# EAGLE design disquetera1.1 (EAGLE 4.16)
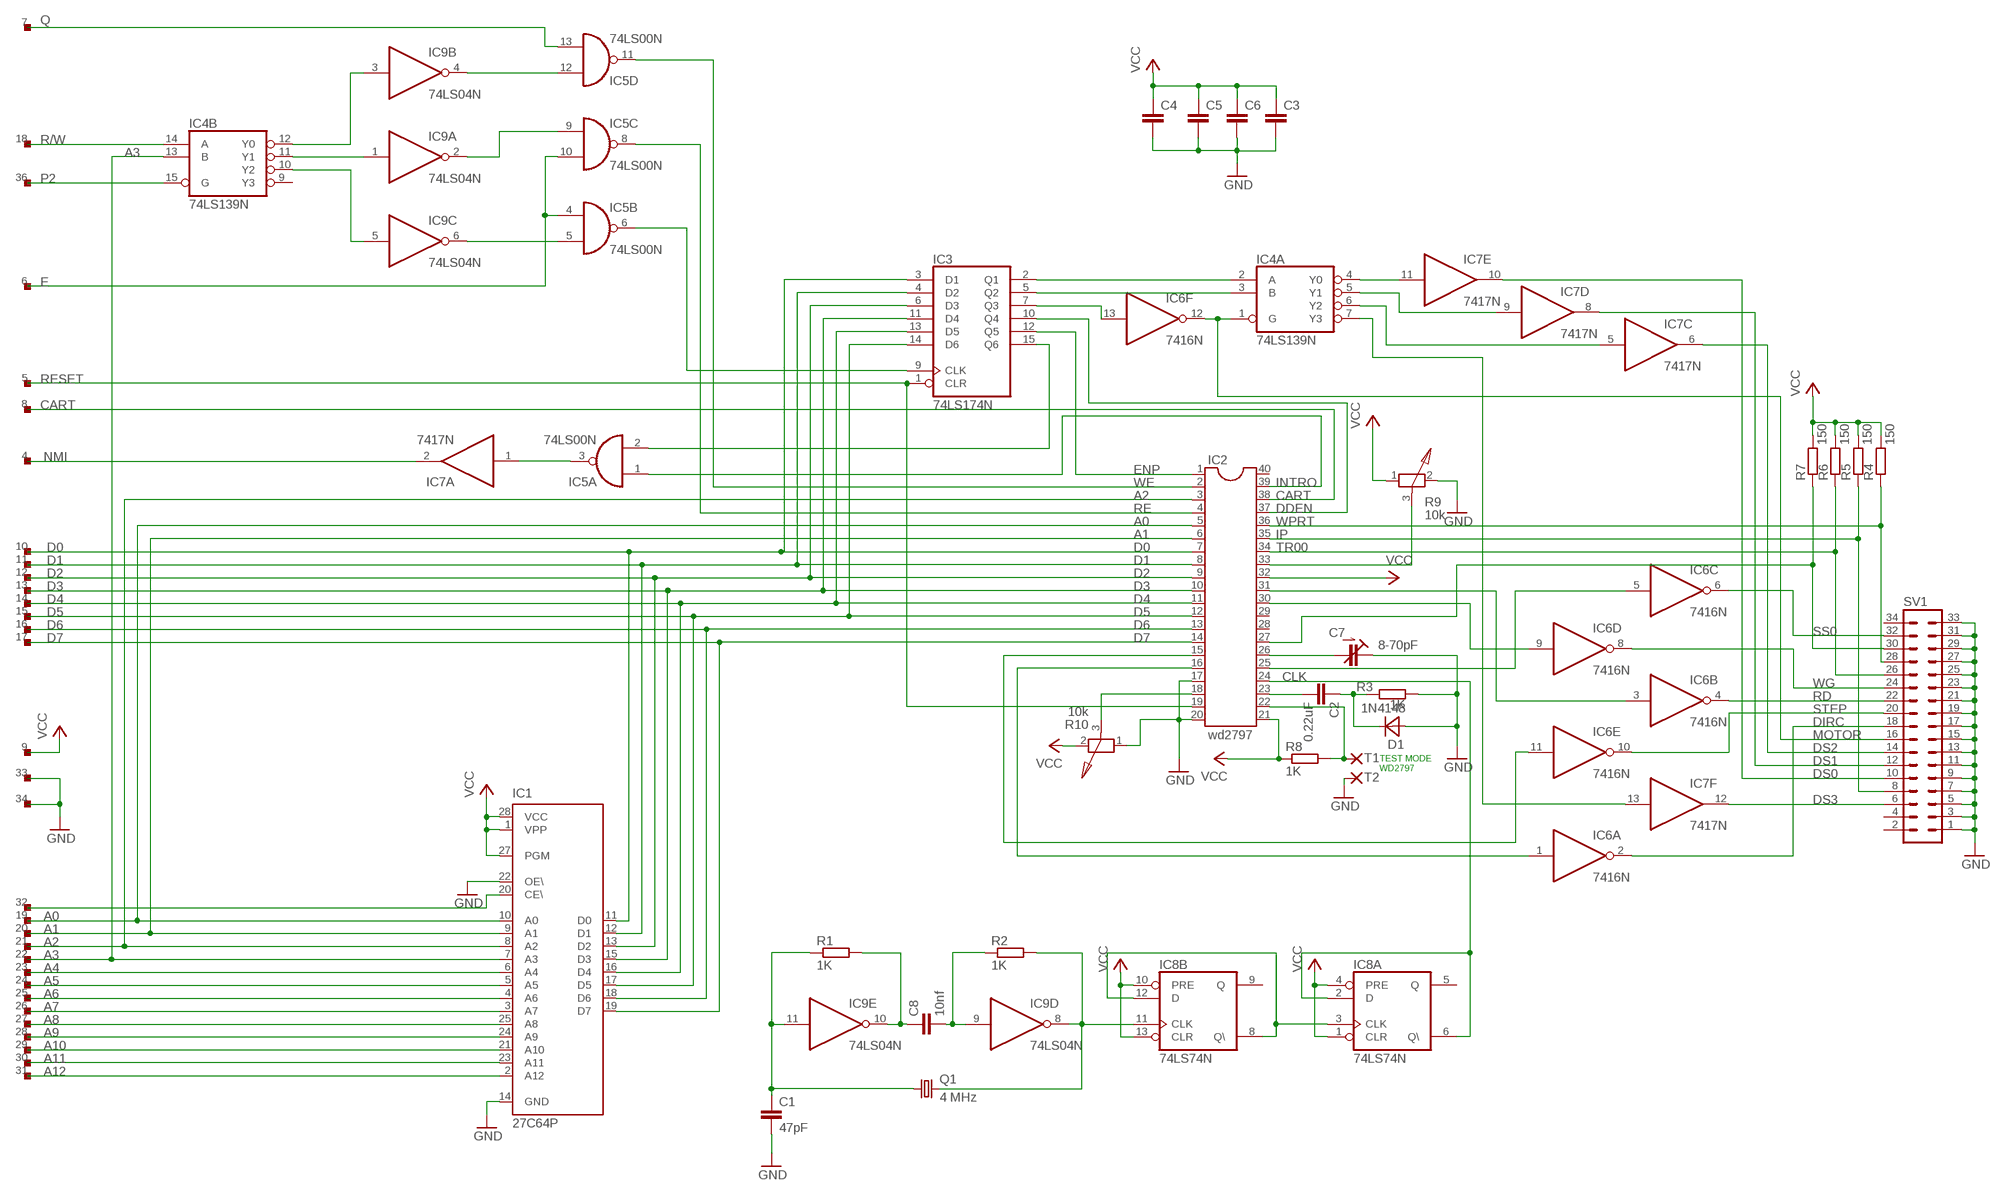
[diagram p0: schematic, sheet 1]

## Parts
C1  47pF  C-EU050-024X044  [C050-024X044]
C2  0.22uF  C-EU050-025X075  [C050-025X075]
C3  C-EU050-025X075  [C050-025X075]
C4  C-EU075-032X103  [C075-032X103]
C5  C-EU075-032X103  [C075-032X103]
C6  C-EU050-030X075  [C050-030X075]
C7  8-70pF  C-TRIMM808  [CTRIM808-BC]
C8  10nf  C-EU050-024X044  [C050-024X044]
D1  1N4148  DIODE-7,5  [D-7,5]
IC1  27C64P  [DIL28-6]
IC2  wd2797  DIL40  [DIL40]
IC3  74LS174N  [DIL16]
IC4  74LS139N  [DIL16]
IC5  74LS00N  [DIL14]
IC6  7416N  [DIL14]
IC7  7417N  [DIL14]
IC8  74LS74N  [DIL14]
IC9  74LS04N  [DIL14]
Q1  4 MHz  CRYSTALHC49S  [HC49/S]
R1  1K  R-EU_0207/2V  [0207/2V]
R2  1K  R-EU_0207/2V  [0207/2V]
R3  1K  R-EU_0207/10  [0207/10]
R4  150  R-EU_0207/10  [0207/10]
R5  150  R-EU_0207/10  [0207/10]
R6  150  R-EU_0207/10  [0207/10]
R7  150  R-EU_0207/10  [0207/10]
R8  1K  R-EU_0207/10  [0207/10]
R9  10k  POT-L  [PT-10]
R10  10k  POT-L  [PT-10]
SV1  ML34L  [ML34L]
T1  1,27/0,8-REDONDO0,80,8  [1,27/0,8-REDONDO]
T2  1,27/0,8-REDONDO0,80,8  [1,27/0,8-REDONDO]
U$1  DRAGON32_H  [BUS_DRAGON32_H]

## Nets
A0: IC1.10(A0) IC2.5 U$1.19
A1: IC1.9(A1) IC2.6 U$1.20
A2: IC1.8(A2) IC2.3 U$1.21
A3: IC1.7(A3) IC4.13(B:B) U$1.22
A4: IC1.6(A4) U$1.23
A5: IC1.5(A5) U$1.24
A6: IC1.4(A6) U$1.25
A7: IC1.3(A7) U$1.26
A8: IC1.25(A8) U$1.27
A9: IC1.24(A9) U$1.28
A10: IC1.21(A10) U$1.29
A11: IC1.23(A11) U$1.30
A12: IC1.2(A12) U$1.31
CART: IC2.38 U$1.8
CLK: IC2.24 IC8.2(A:D) IC8.6(A:Q\)
D0: IC1.11(D0) IC2.7 IC3.3(D1) U$1.10
D1: IC1.12(D1) IC2.8 IC3.4(D2) U$1.11
D2: IC1.13(D2) IC2.9 IC3.6(D3) U$1.12
D3: IC1.15(D3) IC2.10 IC3.11(D4) U$1.13
D4: IC1.16(D4) IC2.11 IC3.13(D5) U$1.14
D5: IC1.17(D5) IC2.12 IC3.14(D6) U$1.15
D6: IC1.18(D6) IC2.13 U$1.16
D7: IC1.19(D7) IC2.14 U$1.17
DDEN: IC2.37 IC3.10(Q4)
DIRC: IC6.2(A:O) SV1.18
DS0: IC7.10(E:O) SV1.10
DS1: IC7.8(D:O) SV1.12
DS2: IC7.6(C:O) SV1.14
DS3: IC7.12(F:O) SV1.6
E: IC5.4(B:I0) IC5.10(C:I1) U$1.6
ENP: IC2.1 IC3.12(Q5)
GND: C1.2 C3.2 C4.2 C5.2 C6.2 C7.1(E) D1.1(A) IC1.14(GND) IC1.22(OE\) IC2.17 IC2.20 R3.2 R9.2 R10.1 SV1.1 SV1.3 SV1.5 SV1.7 SV1.9 SV1.11 SV1.13 SV1.15 SV1.17 SV1.19 SV1.21 SV1.23 SV1.25 SV1.27 SV1.29 SV1.31 SV1.33 T2.1(P) U$1.33 U$1.34
INTRO: IC2.39 IC5.1(A:I0)
IP: IC2.35 R5.1 SV1.8
MOTOR: IC4.1(A:G) IC6.12(F:O) SV1.16
N$1: IC1.20(CE\) U$1.32
N$2: IC3.2(Q1) IC4.2(A:A)
N$3: IC3.5(Q2) IC4.3(A:B)
N$4: IC3.7(Q3) IC6.13(F:I)
N$5: IC2.31 IC6.3(B:I)
N$6: IC4.4(A:Y0) IC7.11(E:I)
N$7: IC4.5(A:Y1) IC7.9(D:I)
N$8: IC4.6(A:Y2) IC7.5(C:I)
N$9: IC4.7(A:Y3) IC7.13(F:I)
N$10: IC5.9(C:I0) IC9.2(A:O)
N$11: IC5.5(B:I1) IC9.6(C:O)
N$12: IC4.11(B:Y1) IC9.1(A:I)
N$13: IC4.10(B:Y2) IC9.5(C:I)
N$14: IC4.12(B:Y0) IC9.3(B:I)
N$15: IC5.12(D:I0) IC9.4(B:O)
N$16: IC3.9(CLK) IC5.6(B:O)
N$17: IC3.15(Q6) IC5.2(A:I1)
N$18: IC5.3(A:O) IC7.1(A:I)
N$20: C1.1 IC9.11(E:I) Q1.1 R1.1
N$21: C8.1 IC9.10(E:O) R1.2
N$22: C8.2 IC9.9(D:I) R2.1
N$23: IC8.11(B:CLK) IC9.8(D:O) Q1.2 R2.2
N$24: IC8.3(A:CLK) IC8.8(B:Q\) IC8.12(B:D)
N$25: C7.2(A) IC2.26
N$26: C2.1 D1.2(K) R3.1
N$27: IC2.30 IC6.9(D:I)
N$28: IC2.15 IC6.11(E:I)
N$29: IC2.16 IC6.1(A:I)
N$30: IC2.25 IC6.5(C:I)
N$31: IC2.27 R7.1 SV1.30
N$33: IC2.22 R8.2 T1.1(P)
N$34: IC2.33 R9.3
N$35: IC2.18 R10.3
NMI: IC7.2(A:O) U$1.4
P2: IC4.15(B:G) U$1.36
PUMP: C2.2 IC2.23
Q: IC5.13(D:I1) U$1.7
R/W: IC4.14(B:A) U$1.18
RD: IC6.4(B:O) SV1.22
RE: IC2.4 IC5.8(C:O)
RESET: IC2.19 IC3.1(CLR) U$1.5
SS0: IC6.6(C:O) SV1.32
STEP: IC6.10(E:O) SV1.20
TR00: IC2.34 R6.1 SV1.26
VCC: C3.1 C4.1 C5.1 C6.1 IC1.1(VPP) IC1.27(PGM) IC1.28(VCC) IC2.21 IC2.32 IC8.1(A:CLR) IC8.4(A:PRE) IC8.10(B:PRE) IC8.13(B:CLR) R4.2 R5.2 R6.2 R7.2 R8.1 R9.1 R10.2 U$1.9
WE: IC2.2 IC5.11(D:O)
WG: IC6.8(D:O) SV1.24
WPRT: IC2.36 R4.1 SV1.28
Unconnected: IC1.26(NC) IC2.28 IC2.29 IC2.40 IC4.9(B:Y3) IC7.3(B:I) IC7.4(B:O) IC8.5(A:Q) IC8.9(B:Q) IC9.12(F:O) IC9.13(F:I) SV1.2 SV1.4 SV1.34 U$1.1 U$1.2 U$1.3 U$1.35 U$1.37 U$1.38 U$1.39 U$1.40

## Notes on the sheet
- TEST MODE
- WD2797

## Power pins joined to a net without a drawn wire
GND: IC3.8(GND) IC4.8(P:GND) IC5.7(P:GND) IC6.7(P:GND) IC7.7(P:GND) IC8.7(P:GND) IC9.7(P:GND)
VCC: IC3.16(VCC) IC4.16(P:VCC) IC5.14(P:VCC) IC6.14(P:VCC) IC7.14(P:VCC) IC8.14(P:VCC) IC9.14(P:VCC)

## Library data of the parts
C1-C6 C8 = rcl:C-EU: CAPACITOR, European symbol
C7 = rcl:C-TRIMM: Trimm capacitor
D1 = discrete:DIODE-7,5
IC1 = microchip:27*64: CMOS EPROM 64 K (8 K x 8), low voltage
IC2 = ic-package:DIL40: Dual In Line
IC3 = 74xx-eu:74*174: Hex D type FLIP FLOP, clear
IC4 = 74xx-eu:74*139: Dual 2-line to 4-line DECODER/DEMULTIPLEXER
IC5 = 74xx-eu:74*00: Quad 2-input NAND gate
IC6 = 74xx-eu:74*16: Hex INVERTER, open collector, high-voltage
IC7 = 74xx-eu:74*17: Hex open collector, high-voltage
IC8 = 74xx-eu:74*74: Dual D type positive edge triggered FLIP FLOP, preset and clear
IC9 = 74xx-eu:74*04: Hex INVERTER
Q1 = crystal:CRYSTAL: CRYSTAL
R1-R8 = rcl:R-EU_: RESISTOR, European symbol
R9 R10 = discrete:POT-L
SV1 = con-harting-ml:ML34: HARTING
T1 T2 = wirepad2:1,27/0,8-REDONDO
U$1 = conectores-ordenadores:DRAGON32_H

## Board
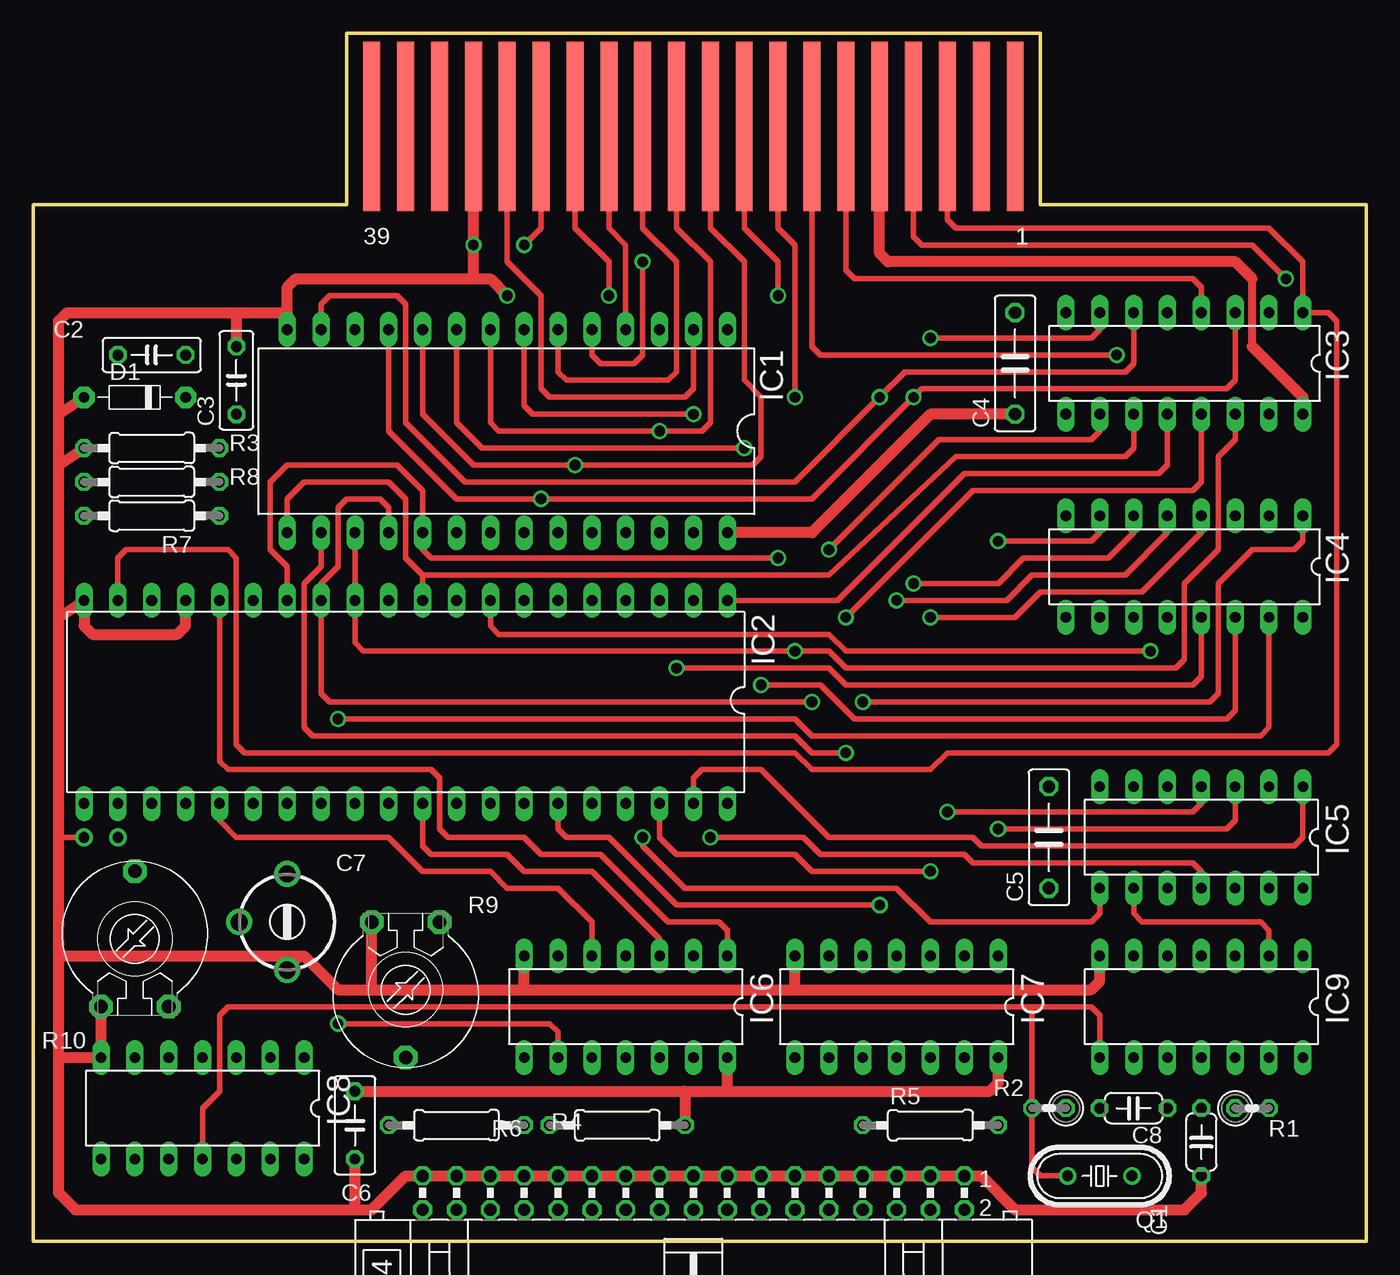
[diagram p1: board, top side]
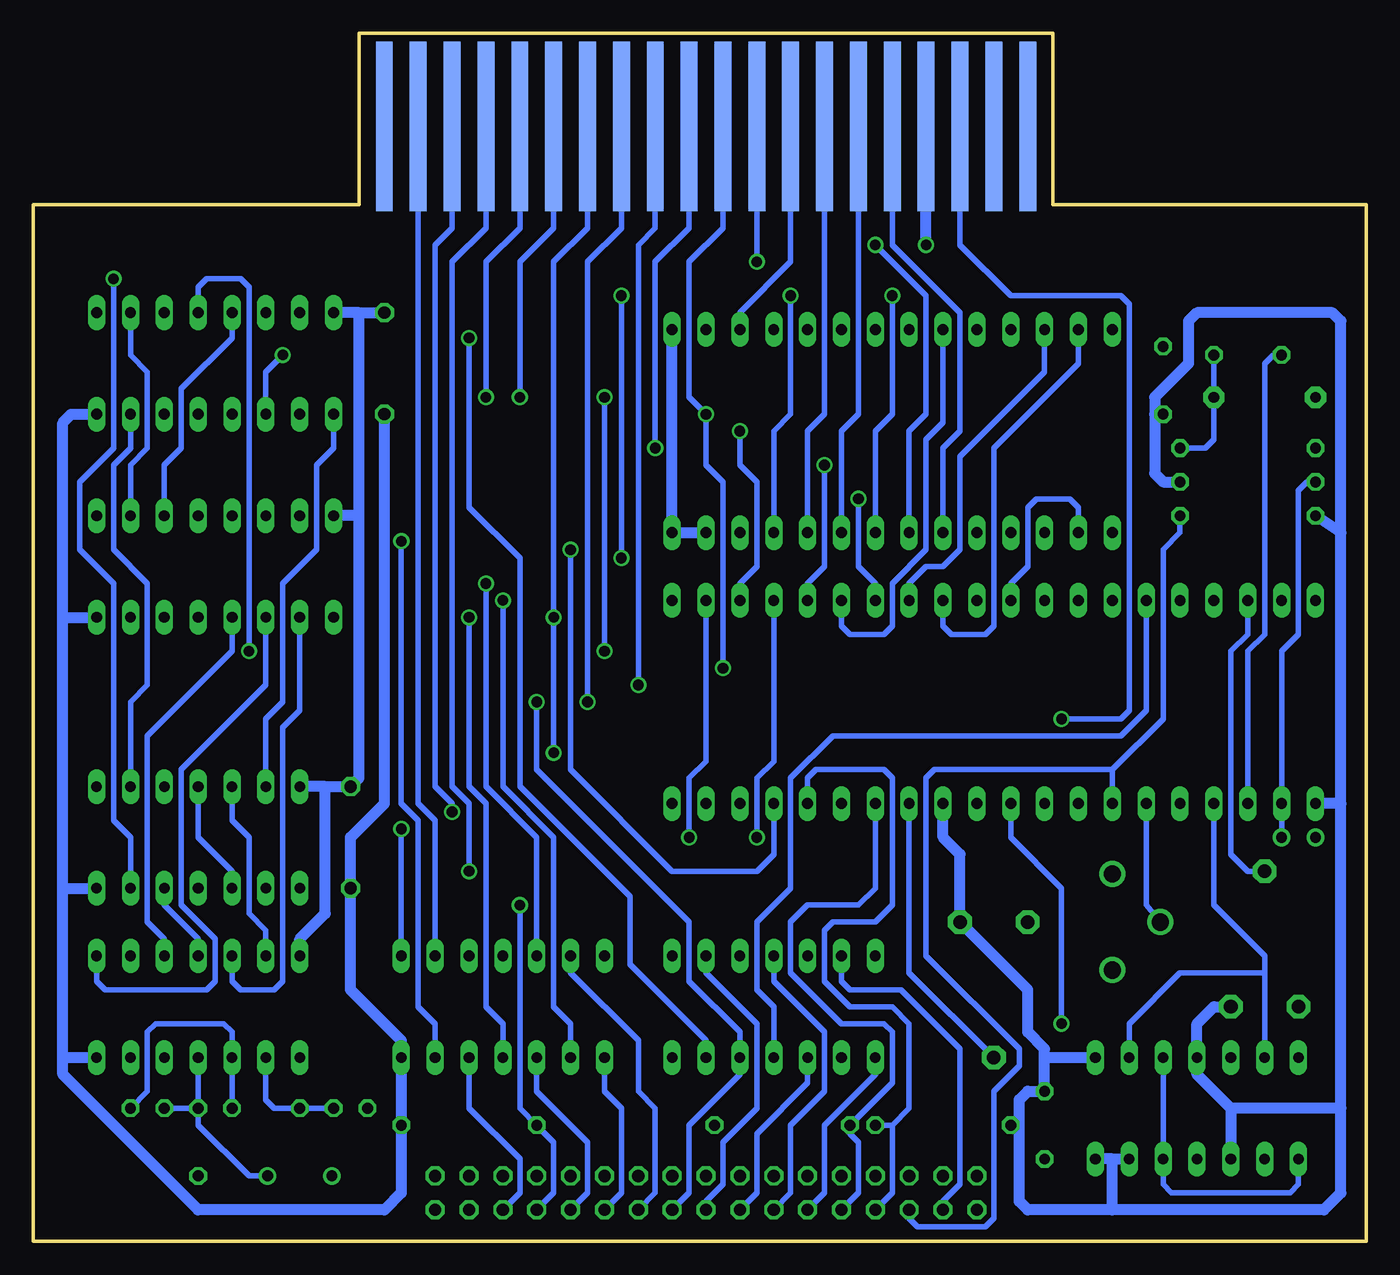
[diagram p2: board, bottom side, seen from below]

Size 99.99 x 90.64 mm. Coordinates in mm from the lower left corner, seen from the top.
Outline: 0,0 99.99,0 99.99,77.77 75.56,77.77 75.56,90.64 23.49,90.64 23.49,77.77 0,77.77 0,0
Copper layers (1*16): Top 0.035mm / dielectric 1.5mm / Bottom 0.035mm
Design rules "default": minimum track width 10mil, minimum drill 24mil, track to track 8mil, track to pad 8mil, pad to pad 8mil, via to via 8mil, smd to smd 8mil, copper to edge 40mil, drill to drill 8mil, minimum pad ring 10mil, minimum via ring 8mil, stop-mask expansion 4mil, vias tented up to drill 0mil, thermal gap 10mil

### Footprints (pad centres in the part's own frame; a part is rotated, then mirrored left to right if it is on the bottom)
C050-024X044 = drill 0.813 octagon: 1 -2.54,0; 2 2.54,0
C050-025X075 = drill 0.813 octagon: 1 -2.54,0; 2 2.54,0
C075-032X103 = drill 0.914 octagon: 1 -3.81,0; 2 3.81,0
C050-030X075 = drill 0.813 octagon: 1 -2.54,0; 2 2.54,0
CTRIM808-BC = drill 1.3 round: 1 -3.607,0; 2 0,3.607; 3 3.607,0
D-7,5 = drill 0.813 pad 1.6 octagon: 1 -3.81,0; 2 3.81,0
DIL28-6 = drill 0.813 long: 1 -16.51,-7.62; 2 -13.97,-7.62; 3 -11.43,-7.62; 4 -8.89,-7.62; 5 -6.35,-7.62; 6 -3.81,-7.62; 7 -1.27,-7.62; 8 1.27,-7.62; 9 3.81,-7.62; 10 6.35,-7.62; 11 8.89,-7.62; 12 11.43,-7.62; 13 13.97,-7.62; 14 16.51,-7.62; 15 16.51,7.62; 16 13.97,7.62; 17 11.43,7.62; 18 8.89,7.62; 19 6.35,7.62; 20 3.81,7.62; 21 1.27,7.62; 22 -1.27,7.62; 23 -3.81,7.62; 24 -6.35,7.62; 25 -8.89,7.62; 26 -11.43,7.62; 27 -13.97,7.62; 28 -16.51,7.62
DIL40 = drill 0.813 long: 1 -24.13,-7.62; 2 -21.59,-7.62; 3 -19.05,-7.62; 4 -16.51,-7.62; 5 -13.97,-7.62; 6 -11.43,-7.62; 7 -8.89,-7.62; 8 -6.35,-7.62; 9 -3.81,-7.62; 10 -1.27,-7.62; 11 1.27,-7.62; 12 3.81,-7.62; 13 6.35,-7.62; 14 8.89,-7.62; 15 11.43,-7.62; 16 13.97,-7.62; 17 16.51,-7.62; 18 19.05,-7.62; 19 21.59,-7.62; 20 24.13,-7.62; 21 24.13,7.62; 22 21.59,7.62; 23 19.05,7.62; 24 16.51,7.62; 25 13.97,7.62; 26 11.43,7.62; 27 8.89,7.62; 28 6.35,7.62; 29 3.81,7.62; 30 1.27,7.62; 31 -1.27,7.62; 32 -3.81,7.62; 33 -6.35,7.62; 34 -8.89,7.62; 35 -11.43,7.62; 36 -13.97,7.62; 37 -16.51,7.62; 38 -19.05,7.62; 39 -21.59,7.62; 40 -24.13,7.62
DIL16 = drill 0.813 long: 1 -8.89,-3.81; 2 -6.35,-3.81; 3 -3.81,-3.81; 4 -1.27,-3.81; 5 1.27,-3.81; 6 3.81,-3.81; 7 6.35,-3.81; 8 8.89,-3.81; 9 8.89,3.81; 10 6.35,3.81; 11 3.81,3.81; 12 1.27,3.81; 13 -1.27,3.81; 14 -3.81,3.81; 15 -6.35,3.81; 16 -8.89,3.81
DIL14 = drill 0.8 long: 1 -7.62,-3.81; 2 -5.08,-3.81; 3 -2.54,-3.81; 4 0,-3.81; 5 2.54,-3.81; 6 5.08,-3.81; 7 7.62,-3.81; 8 7.62,3.81; 9 5.08,3.81; 10 2.54,3.81; 11 0,3.81; 12 -2.54,3.81; 13 -5.08,3.81; 14 -7.62,3.81
HC49/S = drill 0.813 round: 1 -2.413,0; 2 2.413,0
0207/2V = drill 0.813 octagon: 1 -1.27,0; 2 1.27,0
0207/10 = drill 0.813 octagon: 1 -5.08,0; 2 5.08,0
PT-10 = drill 1.016 pad 1.778 octagon: 1 -2.54,-5.08; 2 2.54,-5.08; 3 0,5.08
ML34L = drill 0.914 octagon: 1 -20.32,-1.27; 2 -20.32,1.27; 3 -17.78,-1.27; 4 -17.78,1.27; 5 -15.24,-1.27; 6 -15.24,1.27; 7 -12.7,-1.27; 8 -12.7,1.27; 9 -10.16,-1.27; 10 -10.16,1.27; 11 -7.62,-1.27; 12 -7.62,1.27; 13 -5.08,-1.27; 14 -5.08,1.27; 15 -2.54,-1.27; 16 -2.54,1.27; 17 0,-1.27; 18 0,1.27; 19 2.54,-1.27; 20 2.54,1.27; 21 5.08,-1.27; 22 5.08,1.27; 23 7.62,-1.27; 24 7.62,1.27; 25 10.16,-1.27; 26 10.16,1.27; 27 12.7,-1.27; 28 12.7,1.27; 29 15.24,-1.27; 30 15.24,1.27; 31 17.78,-1.27; 32 17.78,1.27; 33 20.32,-1.27; 34 20.32,1.27
1,27/0,8-REDONDO = drill 0.813 pad 1.27 round: 1 0,0
BUS_DRAGON32_H = smd 1.27 x 12.7: 1 -0.635,6.35; 3 -3.175,6.35; 5 -5.715,6.35; 7 -8.255,6.35; 9 -10.795,6.35; 11 -13.335,6.35; 13 -15.875,6.35; 15 -18.415,6.35; 17 -20.955,6.35; 19 -23.495,6.35; 21 -26.035,6.35; 23 -28.575,6.35; 25 -31.115,6.35; 27 -33.655,6.35; 29 -36.195,6.35; 31 -38.735,6.35; 33 -41.275,6.35; 35 -43.815,6.35; 37 -46.355,6.35; 39 -48.895,6.35 | smd 1.27 x 12.7 bottom: 2 -0.635,6.35; 4 -3.175,6.35; 6 -5.715,6.35; 8 -8.255,6.35; 10 -10.795,6.35; 12 -13.335,6.35; 14 -15.875,6.35; 16 -18.415,6.35; 18 -20.955,6.35; 20 -23.495,6.35; 22 -26.035,6.35; 24 -28.575,6.35; 26 -31.115,6.35; 28 -33.655,6.35; 30 -36.195,6.35; 32 -38.735,6.35; 34 -41.275,6.35; 36 -43.815,6.35; 38 -46.355,6.35; 40 -48.895,6.35

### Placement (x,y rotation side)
C1  87.62,7.46 270 top
C2  8.88,66.51 180 top
C3  15.23,64.6 90 top
C4  73.66,65.88 90 top
C5  76.2,30.32 90 top
C6  24.12,8.73 270 top
C7  19.05,23.96 90 top
C8  82.55,10 180 top
D1  7.62,63.34 0 top
IC1  35.55,60.8 180 top
IC2  27.94,40.48 180 top
IC3  86.36,65.88 180 top
IC4  86.36,50.63 180 top
IC5  87.62,30.32 180 top
IC6  44.45,17.62 180 top
IC7  64.77,17.62 180 top
IC8  12.69,10 180 top
IC9  87.62,17.62 180 top
Q1  80.01,4.92 180 top
R1  91.44,10 0 top
R2  76.2,10 180 top
R3  8.88,59.52 180 top
R4  31.75,8.73 180 top
R5  67.31,8.73 0 top
R6  43.81,8.73 0 top
R7  8.88,54.45 180 top
R8  8.88,56.98 180 top
R9  27.94,18.89 180 top
R10  7.62,22.7 0 top
SV1  49.52,3.65 180 top
T1  6.34,30.32 0 top
T2  3.81,30.32 0 top
U$1  74.29,77.3 0 top

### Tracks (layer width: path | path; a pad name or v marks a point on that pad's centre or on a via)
A0  (via drill 0.8)
  Top 0.406: U$1.19 50.79,76.03 53.34,73.49 53.34,64.6 54.6,63.34 54.6,58.89 53.97,58.26 v40.63,58.26 33.02,58.26 29.21,62.06 IC1.10
  Bottom 0.406: IC2.5 41.9,49.37 40.63,50.63 v40.63,58.26
A1  (via drill 0.8)
  Top 0.406: v53.34,59.52 33.65,59.52 31.75,61.43 IC1.9
  Bottom 0.406: v53.34,59.52 53.34,73.49 50.79,76.03 U$1.20 | IC2.6 39.36,46.19 38.73,45.55 36.19,45.55 35.55,46.19 35.55,49.37 33.02,51.91 33.02,60.16 31.75,61.43 IC1.9
A2  (via drill 0.8)
  Top 0.406: U$1.21 48.25,76.03 50.79,73.49 50.79,61.43 50.16,60.8 v46.98,60.8 34.92,60.8 34.28,61.43 IC1.8
  Bottom 0.406: IC2.3 46.98,49.37 45.71,50.63 45.71,56.98 46.98,58.26 v46.98,60.8
A3  (via drill 0.8)
  Top 0.406: v49.52,62.06 37.46,62.06 36.82,62.7 IC1.7 | v48.25,43.02 59.68,43.02 60.95,41.74 86.99,41.74 87.62,42.38 IC4.13
  Bottom 0.406: U$1.22 48.25,76.03 50.79,73.49 50.79,63.34 v49.52,62.06 49.52,58.26 48.25,56.98 v48.25,43.02
A4
  Top 0.406: U$1.23 45.71,76.03 48.25,73.49 48.25,65.24 47.62,64.6 40,64.6 39.36,65.24 IC1.6
A5  (via drill 0.8)
  Top 0.406: IC1.5 41.9,66.51 42.54,65.88 45.08,65.88 45.71,66.51 v45.71,73.49
  Bottom 0.406: v45.71,73.49 U$1.24
A6
  Top 0.406: U$1.25 43.17,76.03 44.45,74.77 IC1.4
A7
  Bottom 0.406: IC1.3 46.98,69.68 43.17,73.49 U$1.26
A8  (via drill 0.8)
  Top 0.406: v43.17,70.95 43.17,73.49 40.63,76.03 U$1.27
  Bottom 0.406: v43.17,70.95 43.17,62.06 44.45,60.8 IC1.25
A9
  Bottom 0.406: U$1.28 40.63,62.06 41.9,60.8 IC1.24
A10  (via drill 0.8)
  Top 0.406: v36.82,74.77 38.09,76.03 U$1.29
  Bottom 0.406: v36.82,74.77 33.02,70.95 33.02,62.06 34.28,60.8 IC1.21
A11
  Bottom 0.406: U$1.30 38.09,62.06 39.36,60.8 IC1.23
A12
  Top 0.406: U$1.31 35.55,73.49 38.09,70.95 38.09,63.97 38.73,63.34 48.89,63.34 49.52,63.97 IC1.2
CART  (via drill 0.8)
  Top 0.406: v67.31,27.78 58.41,27.78 57.14,29.05 48.25,29.05 46.98,30.32 IC2.38
  Bottom 0.406: U$1.8 66.04,76.03 68.58,73.49 68.58,34.12 67.31,32.86 v67.31,27.78
CLK
  Bottom 0.406: IC2.24 11.42,25.23 7.62,21.43 7.62,20.16 | IC8.6 7.62,20.16 | IC8.2 17.78,16.35 13.96,20.16 7.62,20.16
D0  (via drill 0.8)
  Top 0.406: IC1.11 26.67,60.8 31.75,55.72 v38.09,55.72 58.41,55.72 v66.04,63.34 66.67,63.97 89.53,63.97 90.17,64.6 IC3.3
  Bottom 0.406: v38.09,55.72 38.09,50.63 36.82,49.37 IC2.7 | v66.04,63.34 66.04,73.49 63.49,76.03 U$1.10
D1  (via drill 0.8)
  Top 0.406: U$1.11 60.95,72.86 61.59,72.22 86.99,72.22 87.62,71.59 IC3.4 | v83.81,44.29 60.95,44.29 59.68,45.55 34.92,45.55 34.28,46.19 IC2.8
  Bottom 0.406: v83.81,44.29 83.81,71.59 84.45,72.22 86.99,72.22 87.62,71.59 IC3.4 | IC1.12 24.12,65.24 30.48,58.89 30.48,51.91 31.75,50.63 33.02,50.63 34.28,49.37 IC2.8
D2  (via drill 0.8)
  Top 0.406: IC1.13 21.59,70.32 22.22,70.95 27.3,70.95 27.94,70.32 27.94,61.43 32.38,56.98 57.14,56.98 v63.49,63.34 65.4,65.24 81.91,65.24 82.55,65.88 IC3.6
  Bottom 0.406: v63.49,63.34 63.49,73.49 60.95,76.03 U$1.12 | IC2.9 31.75,46.19 31.11,45.55 28.57,45.55 27.94,46.19 27.94,59.52 21.59,65.88 IC1.13
D3  (via drill 0.8)
  Top 0.406: v81.28,66.51 59.05,66.51 58.41,67.14 U$1.13 | IC3.11 82.55,59.52 81.91,58.89 69.21,58.89 59.68,50 29.21,50 | IC1.15 19.05,55.72 20.32,56.98 26.67,56.98 27.94,55.72 27.94,51.27 29.21,50 | 29.21,50 IC2.10
  Bottom 0.406: IC3.11 82.55,65.24 v81.28,66.51
D4  (via drill 0.8)
  Top 0.406: v60.95,46.83 70.48,56.35 86.99,56.35 87.62,56.98 IC3.13 | v60.95,36.66 58.41,36.66 57.14,37.94 20.95,37.94 20.32,38.57 20.32,49.37 21.59,50.63 IC1.16
  Bottom 0.406: U$1.14 58.41,76.03 60.95,73.49 v60.95,46.83 v60.95,36.66 | IC2.11 26.67,49.37 25.39,50.63 25.39,55.08 24.76,55.72 22.22,55.72 21.59,55.08 IC1.16
D5  (via drill 0.8)
  Top 0.406: v57.14,63.34 57.14,74.77 55.88,76.03 U$1.15 | IC1.17 IC2.12 24.12,44.92 24.76,44.29 v57.14,44.29 59.68,44.29 60.95,43.02 85.72,43.02 86.36,43.65 86.36,49.37 88.9,51.91 88.9,58.89 90.17,60.16 IC3.14
  Bottom 0.406: v57.14,44.29 v57.14,63.34
D6  (via drill 0.8)
  Top 0.406: v58.41,40.48 22.22,40.48 21.59,41.11 IC2.13 21.59,49.37 22.86,50.63 22.86,55.08 23.49,55.72 26.03,55.72 26.67,55.08 IC1.18
  Bottom 0.406: v58.41,40.48 58.41,73.49 55.88,76.03 U$1.16
D7  (via drill 0.8)
  Top 0.406: v55.88,70.95 55.88,73.49 53.34,76.03 U$1.17 | IC2.14 19.05,50.63 17.78,51.91 17.78,56.98 19.05,58.26 27.3,58.26 29.21,56.35 IC1.19 29.21,51.91 29.84,51.27 v55.88,51.27
  Bottom 0.406: v55.88,51.27 v55.88,70.95
DDEN  (via drill 0.8)
  Top 0.406: v59.68,51.91 67.94,60.16 79.37,60.16 80.01,60.8 IC3.10
  Bottom 0.406: v59.68,51.91 59.68,35.4 52.06,27.78 45.71,27.78 44.45,29.05 IC2.37
DIRC
  Bottom 0.406: IC6.2 49.52,20.16 45.71,16.35 45.71,10 48.25,7.46 48.25,4.28 49.52,3.01 SV1.18
DS0
  Bottom 0.406: IC7.10 62.22,11.27 58.41,7.46 58.41,3.65 SV1.10
DS1
  Bottom 0.406: IC7.8 57.14,11.27 55.88,10 55.88,3.65 SV1.12
DS2
  Bottom 0.406: IC7.6 59.68,20.16 54.6,15.08 54.6,11.27 53.34,10 53.34,3.65 SV1.14
DS3
  Bottom 0.406: SV1.6 63.49,3.65 63.49,6.18 67.31,10 IC7.12
E  (via drill 0.8)
  Top 0.406: v68.58,32.22 86.99,32.22 87.62,32.86 IC5.4
  Bottom 0.406: v68.58,32.22 68.58,32.86 69.84,34.12 69.84,74.77 68.58,76.03 U$1.6 | IC5.10 85.09,27.78 87.62,30.32 IC5.4
ENP
  Top 0.406: IC2.1 60.32,48.09 69.84,57.62 84.45,57.62 85.09,58.26 IC3.12
GND  (via drill 0.8)
  Top 0.406: 1.9,30.32 T2.1
  Top 0.813: C1.2 87.62,3.65 86.36,2.38 73.66,2.38 71.12,4.92 SV1.1 SV1.3 SV1.5 SV1.7 SV1.9 SV1.11 SV1.13 SV1.15 SV1.17 SV1.19 SV1.21 SV1.23 SV1.25 SV1.27 SV1.29 SV1.31 SV1.33 27.94,4.92 25.39,2.38 24.12,2.38 | 33.02,72.22 19.68,72.22 19.05,71.59 IC1.14 19.05,69.68 15.23,69.68 | 33.02,72.22 34.28,72.22 v35.55,70.95 | 15.23,69.68 2.54,69.68 1.9,69.05 1.9,62.06 | 1.9,46.83 1.9,58.26 | 1.9,58.26 1.9,62.06 | 1.9,46.83 IC2.20 3.81,46.19 4.44,45.55 10.79,45.55 11.42,46.19 IC2.17 | 1.9,13.81 IC8.7 R10.1 | 1.9,13.81 1.9,21.43 | 1.9,21.43 1.9,30.32 1.9,46.83 | 1.9,13.81 1.9,3.65 3.17,2.38 24.12,2.38 | 24.12,2.38 C6.2 | 25.39,18.89 22.86,18.89 20.32,21.43 | 25.39,18.89 36.82,18.89 | 36.82,18.89 IC6.7 | 57.14,18.89 IC7.7 | 36.82,18.89 57.14,18.89 | 57.14,18.89 79.37,18.89 80.01,19.52 IC9.7 | 25.39,18.89 R9.2 | U$1.34 v33.02,74.77 33.02,72.22 | 15.23,69.68 C3.2 | 1.9,58.26 R3.2 | 1.9,62.06 D1.1 | C7.1 19.25,20.99 20.32,21.43 | 1.9,21.43 20.32,21.43
  Bottom 0.406: IC1.22 36.82,60.8 35.55,62.06 v35.55,70.95
  Bottom 0.813: 75.56,54.45 IC4.8 | 75.56,54.45 75.56,34.76 C5.2 78.1,34.12 | 75.56,54.45 75.56,69.68 | 75.56,69.68 IC3.8 | IC9.7 80.01,22.7 78.1,24.6 78.1,34.12 | 78.1,34.12 IC5.7 | 75.56,69.68 C4.2 | v33.02,74.77 U$1.34
INTRO
  Top 0.406: IC5.1 95.25,30.32 94.61,29.68 71.12,29.68 70.48,30.32 59.68,30.32 54.6,35.4 50.16,35.4 49.52,34.76 IC2.39
IP  (via drill 0.8)
  Top 0.406: v63.49,25.23 48.25,25.23 43.17,30.32 40,30.32 39.36,30.95 IC2.35
  Bottom 0.406: SV1.8 60.95,3.65 60.95,7.46 R5.1 63.49,10 v63.49,25.23
MOTOR  (via drill 0.8)
  Top 0.406: v62.22,40.48 88.26,40.48 88.9,41.11 88.9,49.37 91.44,51.91 94.61,51.91 95.25,52.54 IC4.1
  Bottom 0.406: v62.22,40.48 62.22,35.4 50.79,23.96 50.79,19.52 46.98,15.71 IC6.12 46.98,12.54 50.79,8.73 50.79,3.65 SV1.16
N$1
  Bottom 0.406: U$1.32 35.55,74.77 30.48,69.68 30.48,60.8 31.75,59.52 IC1.20
N$2
  Bottom 0.406: IC4.2 92.7,58.26 91.44,59.52 91.44,65.24 92.7,66.51 IC3.2
N$3
  Bottom 0.406: IC4.3 90.17,58.26 88.9,59.52 88.9,63.97 85.09,67.78 IC3.5
N$4  (via drill 0.8)
  Top 0.406: v67.31,67.78 79.37,67.78 80.01,68.41 IC3.7
  Bottom 0.406: v67.31,67.78 67.31,55.08 63.49,51.27 63.49,34.12 55.24,25.87 55.24,20.79 49.52,15.08 IC6.13
N$5
  Top 0.406: IC6.3 46.98,22.7 41.9,27.78 36.82,27.78 35.55,29.05 29.84,29.05 29.21,29.68 IC2.31
N$6  (via drill 0.8)
  Top 0.406: v67.31,46.83 73.66,46.83 75.56,48.73 83.18,48.73 87.62,53.18 IC4.4
  Bottom 0.406: v67.31,46.83 67.31,34.12 66.04,32.86 66.04,17.62 64.77,16.35 IC7.11
N$7  (via drill 0.8)
  Top 0.406: v64.77,48.09 73.02,48.09 74.93,50 81.91,50 85.09,53.18 IC4.5
  Bottom 0.406: v64.77,48.09 64.77,34.12 60.95,30.32 60.95,17.62 59.68,16.35 IC7.9
N$8  (via drill 0.8)
  Top 0.406: v66.04,49.37 72.39,49.37 74.29,51.27 80.64,51.27 82.55,53.18 IC4.6
  Bottom 0.406: v66.04,49.37 66.04,34.12 62.22,30.32 IC7.5
N$9  (via drill 0.8)
  Top 0.406: v72.39,52.54 79.37,52.54 80.01,53.18 IC4.7
  Bottom 0.406: v72.39,52.54 72.39,32.86 71.12,31.59 71.12,17.62 69.84,16.35 IC7.13
N$10
  Top 0.406: IC5.9 82.55,24.6 83.18,23.96 92.07,23.96 92.7,23.33 IC9.2
N$11
  Bottom 0.406: IC5.5 85.09,31.59 83.81,30.32 83.81,24.6 82.55,23.33 IC9.6
N$12
  Bottom 0.406: IC4.11 82.55,41.74 88.9,35.4 88.9,25.23 86.36,22.7 86.36,19.52 86.99,18.89 94.61,18.89 95.25,19.52 IC9.1
N$13
  Bottom 0.406: IC4.10 80.01,39.84 81.28,38.57 81.28,19.52 81.91,18.89 84.45,18.89 85.09,19.52 IC9.5
N$14
  Bottom 0.406: IC4.12 85.09,44.29 91.44,37.94 91.44,23.96 90.17,22.7 IC9.3
N$15
  Bottom 0.406: IC9.4 87.62,22.7 90.17,25.23 IC5.12
N$16
  Bottom 0.406: IC5.6 82.55,39.2 81.28,40.48 81.28,49.37 78.73,51.91 78.73,58.26 77.47,59.52 IC3.9
N$17
  Bottom 0.406: IC5.2 92.7,40.48 91.44,41.74 91.44,49.37 93.98,51.91 93.98,58.26 92.7,59.52 IC3.15
N$18  (via drill 0.8)
  Top 0.406: v72.39,30.95 89.53,30.95 90.17,31.59 IC5.3
  Bottom 0.406: IC7.1 v72.39,30.95
N$20
  Bottom 0.406: Q1.1 83.81,4.92 87.62,8.73 C1.1 | C1.1 IC9.11 | C1.1 R1.1
N$21
  Bottom 0.406: C8.1 IC9.10 85.09,15.71 85.72,16.35 90.8,16.35 91.44,15.71 91.44,11.27 R1.2
N$22
  Bottom 0.406: R2.1 C8.2 81.91,10 82.55,10.63 IC9.9
N$23
  Top 0.406: IC8.11 12.69,10 13.96,11.27 13.96,16.98 14.6,17.62 74.93,17.62 | 74.93,17.62 79.37,17.62 80.01,16.98 IC9.8 | 74.93,17.62 R2.2 74.93,5.55 75.56,4.92 Q1.2
N$24
  Bottom 0.406: IC8.3 IC8.12 15.23,4.28 14.6,3.65 5.71,3.65 5.08,4.28 IC8.8
N$25
  Bottom 0.406: IC2.26 16.51,25.23 C7.2
N$26
  Bottom 0.406: R3.1 12.06,59.52 11.42,60.16 D1.2 C2.1
N$27  (via drill 0.8)
  Top 0.406: v22.86,16.35 38.73,16.35 39.36,15.71 IC6.9
  Bottom 0.406: v22.86,16.35 22.86,26.51 26.67,30.32 IC2.30
N$28
  Bottom 0.406: IC6.11 44.45,17.62 45.71,18.89 45.71,23.96 43.17,26.51 43.17,34.76 40,37.94 18.41,37.94 16.51,39.84 IC2.15
N$29
  Top 0.406: IC6.1 52.06,23.33 51.43,23.96 47.62,23.96 42.54,29.05 38.09,29.05 36.82,30.32 31.11,30.32 30.48,30.95 30.48,34.76 29.84,35.4 14.6,35.4 13.96,36.03 IC2.16
N$30
  Top 0.406: IC6.5 41.9,23.96 39.36,26.51 35.55,26.51 34.28,27.78 29.21,27.78 26.67,30.32 15.23,30.32 13.96,31.59 IC2.25
N$31
  Bottom 0.406: R7.1 13.96,53.18 15.23,51.91 15.23,39.2 19.05,35.4 | 19.05,35.4 IC2.27 | SV1.30 34.28,1.74 33.65,1.1 28.57,1.1 27.94,1.74 27.94,11.27 26.03,13.17 26.03,14.44 33.02,21.43 33.02,34.76 32.38,35.4 19.05,35.4
N$33
  Bottom 0.406: R8.2 4.44,56.98 5.08,56.35 5.08,45.55 6.34,44.29 IC2.22 T1.1
N$34
  Bottom 0.406: IC2.33 34.28,20.16 R9.3
N$35
  Bottom 0.406: R10.3 8.88,27.78 10.15,29.05 10.15,44.29 8.88,45.55 IC2.18
NMI
  Bottom 0.406: U$1.4 71.12,32.86 69.84,31.59 IC7.2
P2  (via drill 0.8)
  Top 0.406: v22.86,39.2 57.14,39.2 58.41,37.94 92.07,37.94 92.7,38.57 IC4.15
  Bottom 0.406: v22.86,39.2 18.41,39.2 17.78,39.84 17.78,70.32 18.41,70.95 26.67,70.95 30.48,74.77 U$1.36
PUMP
  Bottom 0.406: IC2.23 8.88,44.29 7.62,45.55 7.62,65.88 6.98,66.51 C2.2
Q  (via drill 0.8)
  Top 0.406: v93.98,72.22 91.44,74.77 66.67,74.77 66.04,75.4 U$1.7
  Bottom 0.406: v93.98,72.22 93.98,59.52 96.52,56.98 96.52,51.91 93.98,49.37 93.98,31.59 92.7,30.32 IC5.13
R/W  (via drill 0.8)
  Top 0.406: v54.6,41.74 59.05,41.74 61.59,39.2 89.53,39.2 90.17,39.84 IC4.14
  Bottom 0.406: v54.6,41.74 54.6,74.77 53.34,76.03 U$1.18
RD
  Bottom 0.406: IC6.4 44.45,19.52 40.63,15.71 40.63,11.27 43.17,8.73 43.17,3.65 SV1.22
RE  (via drill 0.8)
  Top 0.406: v45.71,30.32 45.71,29.68 48.89,26.51 64.77,26.51 67.31,23.96 79.37,23.96 80.01,24.6 IC5.8
  Bottom 0.406: v45.71,30.32 45.71,34.76 44.45,36.03 IC2.4
RESET
  Top 0.406: IC2.19 6.34,51.27 6.98,51.91 14.6,51.91 15.23,51.27 15.23,37.3 15.87,36.66 57.14,36.66 58.41,35.4 67.31,35.4 68.58,36.66 97.15,36.66 97.79,37.3 97.79,69.05 97.15,69.68 IC3.1 95.25,73.49 92.7,76.03 69.21,76.03 68.58,76.67 U$1.5
SS0
  Bottom 0.406: IC6.6 39.36,19.52 38.73,18.89 34.92,18.89 30.48,14.44 30.48,4.28 31.75,3.01 SV1.32
STEP
  Bottom 0.406: IC6.10 41.9,11.9 45.71,8.09 45.71,3.65 SV1.20
TR00
  Bottom 0.406: IC2.34 36.82,26.51 38.09,25.23 41.9,25.23 43.17,23.96 43.17,20.16 39.36,16.35 36.19,16.35 35.55,15.71 35.55,11.9 R6.1 38.73,8.09 38.09,7.46 38.09,3.65 SV1.26
VCC
  Top 0.406: 63.49,79.84 U$1.9
  Top 0.61: 91.44,67.14 91.44,72.22
  Top 0.813: IC7.14 72.39,11.9 71.75,11.27 52.06,11.27 | 52.06,11.27 IC6.14 | C6.1 48.89,11.27 | 48.89,11.27 52.06,11.27 | C4.1 67.31,62.06 58.41,53.18 IC1.28 | 63.49,79.84 63.49,74.13 64.13,73.49 90.17,73.49 91.44,72.22 | 91.44,67.14 95.25,63.34 IC3.16 | 48.89,11.27 R6.2
  Bottom 0.813: IC1.27 IC1.28 IC1.1 | 1.9,32.86 1.9,53.18 | 1.9,32.86 IC2.21 | 1.9,10 1.9,3.65 3.17,2.38 19.05,2.38 | 1.9,10 1.9,32.86 | 19.05,2.38 19.05,6.18 | 19.05,6.18 IC8.13 | 19.05,6.18 IC8.14 | 10.15,10 IC8.10 | 1.9,10 10.15,10 | 10.15,10 12.69,12.54 IC8.4 12.69,16.35 11.42,17.62 R10.2 | 26.03,8.73 26.03,3.01 25.39,2.38 19.05,2.38 | 24.12,13.81 IC8.1 | 1.9,53.18 R7.2 | 97.79,13.81 IC9.14 | 97.79,13.81 97.79,26.51 | 97.79,26.51 IC5.14 | 97.79,26.51 97.79,46.83 | 97.79,46.83 IC4.16 | 97.79,46.83 97.79,61.43 97.15,62.06 IC3.16 | IC2.32 31.75,30.32 30.48,29.05 R9.1 25.39,18.89 25.39,15.71 24.12,14.44 24.12,13.81 | 24.12,13.81 C6.1 25.39,11.27 26.03,10.63 26.03,8.73 | 97.79,13.81 97.79,12.54 87.62,2.38 73.66,2.38 72.39,3.65 R5.2 IC7.14 72.39,15.08 76.2,18.89 C5.1 76.2,30.32 73.66,32.86 C4.1 | 26.03,8.73 R4.2 | 15.87,62.06 15.87,63.34 13.33,65.88 13.33,69.05 12.69,69.68 2.54,69.68 1.9,69.05 1.9,53.18 | 15.87,62.06 C3.1 | 15.87,62.06 15.87,57.62 15.23,56.98 R8.1
WE  (via drill 0.8)
  Top 0.406: v50.79,30.32 57.78,30.32 59.05,29.05 69.84,29.05 70.48,28.41 86.99,28.41 87.62,27.78 IC5.11
  Bottom 0.406: v50.79,30.32 50.79,34.76 49.52,36.03 IC2.2
WG
  Bottom 0.406: IC6.8 36.82,12.54 40.63,8.73 40.63,3.65 SV1.24
WPRT
  Bottom 0.406: IC2.36 41.9,34.76 41.27,35.4 36.19,35.4 35.55,34.76 35.55,25.23 36.82,23.96 40,23.96 40.63,23.33 40.63,19.52 38.73,17.62 35.55,17.62 34.28,16.35 34.28,10 35.55,8.73 | SV1.28 35.55,3.65 35.55,8.73 | 35.55,8.73 R4.1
